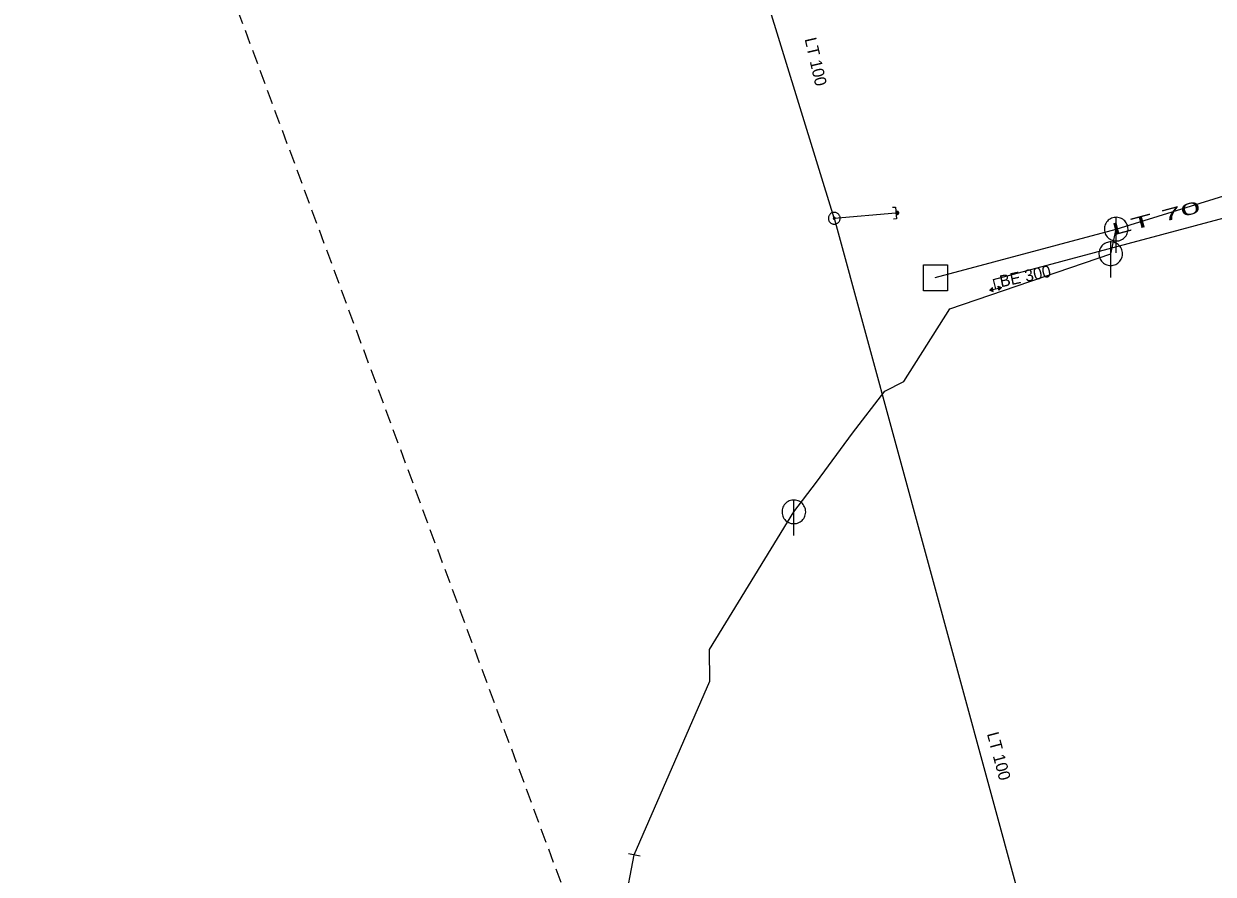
# Model space of a CAD drawing. Extents: x -690254 to -689100, y -975264 to -974703.
# Drawn here: x -689747.9 to -689647.4, y -974992.3 to -974920.4 of the extents above; entities that cross this region are included whole.
import ezdxf

# ---------------------------------------------------------------- set-up
doc = ezdxf.new("R2010")
doc.units = 0
doc.header["$LTSCALE"] = 0.4
doc.linetypes.add('MEDIUM_DASHED', pattern=[4.5, 3, -1.5])
for name, color, linetype, lineweight in [('1', 7, 'Continuous', 13), ('11', 7, 'Continuous', 13), ('14', 7, 'Continuous', 13), ('17', 7, 'Continuous', 25), ('22', 7, 'Continuous', 13), ('28', 7, 'Continuous', 13), ('34', 7, 'Continuous', 13), ('47', 7, 'Continuous', 13), ('63', 7, 'MEDIUM_DASHED', 25), ('9', 7, 'Continuous', 13)]:
    doc.layers.add(name, color=color, linetype=linetype, lineweight=lineweight)

msp = doc.modelspace()

# ---------------------------------------------------------------- linework, layer by layer
at = {"layer": '11'}
msp.add_line((-689656.03, -974939.829), (-689655.57, -974937.75), dxfattribs=at)
for points in [[(-689682.809, -974961.649), (-689680.89, -974959.149), (-689677.85, -974954.989), (-689675.129, -974951.44), (-689673.52, -974950.629), (-689669.64, -974944.5), (-689656.03, -974939.829)], [(-689696.3, -974990.64), (-689689.91, -974975.96), (-689689.94, -974973.28), (-689682.809, -974961.649)], [(-689705.559, -975025.01), (-689705.649, -975017.17), (-689704.62, -975014.579), (-689697.949, -974999.219), (-689696.3, -974990.64)]]:
    msp.add_lwpolyline(points, dxfattribs=at)
at = {"layer": '14'}
msp.add_line((-689674.178, -974936.379), (-689674.067, -974936.377), dxfattribs=at)
at = {"layer": '14', "lineweight": 25}
msp.add_line((-689670.875, -974941.853), (-689655.57, -974937.75), dxfattribs=at)
msp.add_lwpolyline([(-689655.57, -974937.75), (-689631.897, -974930.421), (-689624.679, -974928.186)], dxfattribs=at)
at = {"layer": '17'}
for q in [(-689686.37, -974914.237), (-689674.178, -974936.379), (-689653.94, -975030.302)]:
    msp.add_line((-689679.393, -974936.834), q, dxfattribs=at)
msp.add_lwpolyline([(-689665.933, -974942.022), (-689640.32, -974935.166), (-689625.688, -974930.875), (-689605.756, -974925.377)], dxfattribs=at)
at = {"layer": '22'}
for p, q in [((-689655.57, -974939.75), (-689655.569, -974936.75)), ((-689656.03, -974941.829), (-689656.029, -974938.829)), ((-689682.809, -974963.649), (-689682.808, -974960.649))]:
    msp.add_line(p, q, dxfattribs=at)
for points in [[(-689654.57, -974937.75), (-689654.575, -974937.641), (-689654.593, -974937.533), (-689654.623, -974937.427), (-689654.663, -974937.326), (-689654.715, -974937.229), (-689654.777, -974937.139), (-689654.849, -974937.056), (-689654.929, -974936.982), (-689655.017, -974936.916), (-689655.111, -974936.861), (-689655.211, -974936.816), (-689655.316, -974936.783), (-689655.423, -974936.761), (-689655.532, -974936.751), (-689655.642, -974936.753), (-689655.75, -974936.767), (-689655.857, -974936.792), (-689655.96, -974936.829), (-689656.058, -974936.878), (-689656.15, -974936.936), (-689656.236, -974937.005), (-689656.313, -974937.082), (-689656.382, -974937.168), (-689656.441, -974937.26), (-689656.489, -974937.358), (-689656.526, -974937.461), (-689656.552, -974937.568), (-689656.566, -974937.676), (-689656.569, -974937.786), (-689656.559, -974937.895), (-689656.538, -974938.002), (-689656.504, -974938.106), (-689656.46, -974938.206), (-689656.405, -974938.301), (-689656.339, -974938.389), (-689656.265, -974938.469), (-689656.182, -974938.541), (-689656.092, -974938.603), (-689655.996, -974938.655), (-689655.894, -974938.696), (-689655.789, -974938.726), (-689655.681, -974938.744), (-689655.571, -974938.75), (-689655.462, -974938.744), (-689655.354, -974938.726), (-689655.249, -974938.697), (-689655.147, -974938.656), (-689655.05, -974938.604), (-689654.96, -974938.542), (-689654.877, -974938.471), (-689654.802, -974938.391), (-689654.737, -974938.303), (-689654.681, -974938.209), (-689654.637, -974938.109), (-689654.603, -974938.005), (-689654.581, -974937.897), (-689654.571, -974937.788)], [(-689655.03, -974939.829), (-689655.035, -974939.72), (-689655.053, -974939.612), (-689655.083, -974939.506), (-689655.123, -974939.405), (-689655.175, -974939.308), (-689655.237, -974939.218), (-689655.309, -974939.135), (-689655.389, -974939.061), (-689655.477, -974938.995), (-689655.571, -974938.94), (-689655.671, -974938.895), (-689655.776, -974938.862), (-689655.883, -974938.84), (-689655.992, -974938.83), (-689656.102, -974938.832), (-689656.21, -974938.846), (-689656.317, -974938.871), (-689656.42, -974938.908), (-689656.518, -974938.957), (-689656.61, -974939.015), (-689656.696, -974939.084), (-689656.773, -974939.161), (-689656.842, -974939.247), (-689656.901, -974939.339), (-689656.949, -974939.437), (-689656.986, -974939.54), (-689657.012, -974939.647), (-689657.026, -974939.755), (-689657.029, -974939.865), (-689657.019, -974939.974), (-689656.998, -974940.081), (-689656.964, -974940.185), (-689656.92, -974940.285), (-689656.865, -974940.38), (-689656.799, -974940.468), (-689656.725, -974940.548), (-689656.642, -974940.62), (-689656.552, -974940.682), (-689656.456, -974940.734), (-689656.354, -974940.775), (-689656.249, -974940.805), (-689656.141, -974940.823), (-689656.031, -974940.829), (-689655.922, -974940.823), (-689655.814, -974940.805), (-689655.709, -974940.776), (-689655.607, -974940.735), (-689655.51, -974940.683), (-689655.42, -974940.621), (-689655.337, -974940.55), (-689655.262, -974940.47), (-689655.197, -974940.382), (-689655.141, -974940.288), (-689655.097, -974940.188), (-689655.063, -974940.084), (-689655.041, -974939.976), (-689655.031, -974939.867)], [(-689671.855, -974940.764), (-689669.822, -974940.764), (-689669.822, -974942.957), (-689671.855, -974942.957)], [(-689681.809, -974961.649), (-689681.814, -974961.54), (-689681.832, -974961.432), (-689681.862, -974961.326), (-689681.902, -974961.225), (-689681.954, -974961.128), (-689682.016, -974961.038), (-689682.088, -974960.955), (-689682.168, -974960.881), (-689682.256, -974960.815), (-689682.35, -974960.76), (-689682.45, -974960.715), (-689682.555, -974960.682), (-689682.662, -974960.66), (-689682.771, -974960.65), (-689682.881, -974960.652), (-689682.989, -974960.666), (-689683.096, -974960.691), (-689683.199, -974960.728), (-689683.297, -974960.777), (-689683.389, -974960.835), (-689683.475, -974960.904), (-689683.552, -974960.981), (-689683.621, -974961.067), (-689683.68, -974961.159), (-689683.728, -974961.257), (-689683.765, -974961.36), (-689683.791, -974961.467), (-689683.805, -974961.575), (-689683.808, -974961.685), (-689683.798, -974961.794), (-689683.777, -974961.901), (-689683.743, -974962.005), (-689683.699, -974962.105), (-689683.644, -974962.2), (-689683.578, -974962.288), (-689683.504, -974962.368), (-689683.421, -974962.44), (-689683.331, -974962.502), (-689683.235, -974962.554), (-689683.133, -974962.595), (-689683.028, -974962.625), (-689682.92, -974962.643), (-689682.81, -974962.649), (-689682.701, -974962.643), (-689682.593, -974962.625), (-689682.488, -974962.596), (-689682.386, -974962.555), (-689682.289, -974962.503), (-689682.199, -974962.441), (-689682.116, -974962.37), (-689682.041, -974962.29), (-689681.976, -974962.202), (-689681.92, -974962.108), (-689681.876, -974962.008), (-689681.842, -974961.904), (-689681.82, -974961.796), (-689681.81, -974961.687)]]:
    msp.add_lwpolyline(points, close=True, dxfattribs=at)
at = {"layer": '28'}
msp.add_line((-689696.791, -974990.546), (-689695.809, -974990.734), dxfattribs=at)
at = {"layer": '34'}
for p, q in [((-689666.039, -974942.983), (-689666.093, -974942.762)), ((-689666.011, -974942.997), (-689666.074, -974942.737)), ((-689665.981, -974943.006), (-689666.052, -974942.715)), ((-689665.751, -974942.801), (-689665.932, -974942.022)), ((-689665.546, -974942.581), (-689665.268, -974942.689)), ((-689665.455, -974942.883), (-689665.52, -974942.591)), ((-689665.432, -974942.863), (-689665.49, -974942.601)), ((-689665.413, -974942.838), (-689665.462, -974942.615)), ((-689665.392, -974942.817), (-689665.435, -974942.625)), ((-689665.374, -974942.797), (-689665.409, -974942.635)), ((-689665.35, -974942.776), (-689665.379, -974942.645)), ((-689665.331, -974942.755), (-689665.353, -974942.655)), ((-689665.312, -974942.731), (-689665.325, -974942.669)), ((-689665.287, -974942.71), (-689665.294, -974942.679)), ((-689666.209, -974942.924), (-689666.216, -974942.893)), ((-689666.177, -974942.932), (-689666.192, -974942.871)), ((-689666.149, -974942.945), (-689666.173, -974942.846)), ((-689666.123, -974942.955), (-689666.155, -974942.825)), ((-689666.093, -974942.964), (-689666.132, -974942.802)), ((-689666.067, -974942.974), (-689666.113, -974942.783))]:
    msp.add_line(p, q, dxfattribs=at)
for points in [[(-689666.033, -974942.694), (-689666.235, -974942.913), (-689665.268, -974942.689)], [(-689666.235, -974942.913), (-689665.954, -974943.016), (-689666.033, -974942.694)], [(-689665.268, -974942.689), (-689665.475, -974942.904), (-689665.546, -974942.581)]]:
    msp.add_lwpolyline(points, dxfattribs=at)
at = {"layer": '47'}
for points in [[(-689679.269, -974937.318), (-689679.219, -974937.302), (-689679.171, -974937.281), (-689679.126, -974937.256), (-689679.083, -974937.226), (-689679.043, -974937.191), (-689679.008, -974937.152), (-689678.977, -974937.11), (-689678.95, -974937.065), (-689678.928, -974937.018), (-689678.911, -974936.968), (-689678.899, -974936.917), (-689678.894, -974936.865), (-689678.893, -974936.813), (-689678.898, -974936.761), (-689678.908, -974936.71), (-689678.924, -974936.66), (-689678.945, -974936.612), (-689678.971, -974936.566), (-689679, -974936.524), (-689679.035, -974936.484), (-689679.074, -974936.449), (-689679.116, -974936.417), (-689679.161, -974936.39), (-689679.208, -974936.368), (-689679.258, -974936.352), (-689679.309, -974936.34), (-689679.361, -974936.334), (-689679.413, -974936.334), (-689679.465, -974936.339), (-689679.516, -974936.349), (-689679.566, -974936.365), (-689679.614, -974936.386), (-689679.661, -974936.411), (-689679.702, -974936.441), (-689679.742, -974936.476), (-689679.778, -974936.514), (-689679.809, -974936.556), (-689679.836, -974936.601), (-689679.858, -974936.649), (-689679.874, -974936.699), (-689679.886, -974936.75), (-689679.892, -974936.801), (-689679.892, -974936.854), (-689679.887, -974936.906), (-689679.877, -974936.957), (-689679.861, -974937.007), (-689679.84, -974937.055), (-689679.816, -974937.101), (-689679.785, -974937.143), (-689679.75, -974937.183), (-689679.712, -974937.219), (-689679.67, -974937.249), (-689679.625, -974937.276), (-689679.577, -974937.298), (-689679.527, -974937.315), (-689679.476, -974937.327), (-689679.425, -974937.332), (-689679.372, -974937.333), (-689679.32, -974937.328)], [(-689679.372, -974936.913), (-689679.363, -974936.911), (-689679.356, -974936.907), (-689679.349, -974936.903), (-689679.342, -974936.898), (-689679.335, -974936.892), (-689679.33, -974936.886), (-689679.324, -974936.879), (-689679.32, -974936.872), (-689679.317, -974936.864), (-689679.314, -974936.856), (-689679.312, -974936.847), (-689679.311, -974936.838), (-689679.311, -974936.83), (-689679.311, -974936.822), (-689679.313, -974936.813), (-689679.315, -974936.804), (-689679.319, -974936.797), (-689679.323, -974936.79), (-689679.328, -974936.783), (-689679.334, -974936.776), (-689679.34, -974936.771), (-689679.347, -974936.765), (-689679.354, -974936.761), (-689679.363, -974936.757), (-689679.37, -974936.755), (-689679.379, -974936.753), (-689679.388, -974936.752), (-689679.396, -974936.752), (-689679.404, -974936.752), (-689679.413, -974936.754), (-689679.422, -974936.756), (-689679.429, -974936.76), (-689679.436, -974936.764), (-689679.443, -974936.769), (-689679.45, -974936.775), (-689679.456, -974936.78), (-689679.461, -974936.788), (-689679.465, -974936.795), (-689679.469, -974936.804), (-689679.471, -974936.811), (-689679.473, -974936.82), (-689679.474, -974936.829), (-689679.474, -974936.837), (-689679.474, -974936.845), (-689679.472, -974936.854), (-689679.47, -974936.863), (-689679.466, -974936.87), (-689679.462, -974936.877), (-689679.457, -974936.884), (-689679.451, -974936.891), (-689679.446, -974936.897), (-689679.438, -974936.902), (-689679.431, -974936.906), (-689679.423, -974936.909), (-689679.415, -974936.912), (-689679.406, -974936.914), (-689679.397, -974936.915), (-689679.389, -974936.915), (-689679.381, -974936.915)]]:
    msp.add_lwpolyline(points, close=True, dxfattribs=at)
msp.add_lwpolyline([(-689674.472, -974935.906), (-689674.221, -974935.884), (-689674.134, -974936.873), (-689674.385, -974936.895)], dxfattribs=at)
at = {"layer": '63'}
msp.add_lwpolyline([(-690175.832, -975238.167), (-690201.511, -975156.663), (-690201.511, -975156.663), (-689696.859, -975008.171), (-689696.859, -975008.171), (-689730.354, -974917.735), (-689730.354, -974917.735), (-689127.452, -974763.66), (-689127.452, -974763.66), (-689118.52, -974838.465), (-689118.52, -974838.465), (-689624.288, -974970.21), (-689624.288, -974970.21), (-689593.026, -975070.694), (-689593.026, -975070.694)], close=True, dxfattribs=at)
at = {"layer": '9'}
for points in [[(-689674.193, -974936.377), (-689674.193, -974936.39), (-689674.191, -974936.403), (-689674.188, -974936.416), (-689674.183, -974936.428), (-689674.177, -974936.44), (-689674.17, -974936.451), (-689674.162, -974936.461), (-689674.152, -974936.471), (-689674.142, -974936.479), (-689674.131, -974936.486), (-689674.119, -974936.492), (-689674.107, -974936.497), (-689674.094, -974936.5), (-689674.081, -974936.502), (-689674.068, -974936.504), (-689674.055, -974936.503), (-689674.042, -974936.501), (-689674.029, -974936.498), (-689674.017, -974936.493), (-689674.005, -974936.487), (-689673.994, -974936.48), (-689673.984, -974936.472), (-689673.974, -974936.462), (-689673.966, -974936.452), (-689673.959, -974936.441), (-689673.953, -974936.429), (-689673.948, -974936.417), (-689673.945, -974936.404), (-689673.943, -974936.391), (-689673.941, -974936.378), (-689673.942, -974936.365), (-689673.944, -974936.352), (-689673.947, -974936.339), (-689673.952, -974936.327), (-689673.958, -974936.315), (-689673.965, -974936.304), (-689673.973, -974936.294), (-689673.983, -974936.284), (-689673.993, -974936.276), (-689674.004, -974936.269), (-689674.016, -974936.263), (-689674.028, -974936.258), (-689674.041, -974936.255), (-689674.054, -974936.253), (-689674.067, -974936.252), (-689674.08, -974936.252), (-689674.093, -974936.254), (-689674.106, -974936.257), (-689674.118, -974936.262), (-689674.13, -974936.268), (-689674.141, -974936.275), (-689674.151, -974936.283), (-689674.161, -974936.293), (-689674.169, -974936.303), (-689674.176, -974936.314), (-689674.182, -974936.326), (-689674.187, -974936.338), (-689674.19, -974936.351), (-689674.192, -974936.364)], [(-689674.173, -974936.377), (-689674.174, -974936.388), (-689674.172, -974936.399), (-689674.169, -974936.41), (-689674.165, -974936.42), (-689674.16, -974936.43), (-689674.154, -974936.439), (-689674.147, -974936.448), (-689674.139, -974936.456), (-689674.13, -974936.463), (-689674.121, -974936.469), (-689674.111, -974936.474), (-689674.101, -974936.478), (-689674.09, -974936.481), (-689674.079, -974936.484), (-689674.068, -974936.484), (-689674.057, -974936.484), (-689674.046, -974936.482), (-689674.035, -974936.479), (-689674.025, -974936.475), (-689674.015, -974936.47), (-689674.006, -974936.464), (-689673.997, -974936.457), (-689673.989, -974936.449), (-689673.982, -974936.44), (-689673.976, -974936.431), (-689673.971, -974936.421), (-689673.967, -974936.411), (-689673.964, -974936.4), (-689673.962, -974936.389), (-689673.961, -974936.378), (-689673.961, -974936.367), (-689673.963, -974936.356), (-689673.966, -974936.345), (-689673.97, -974936.335), (-689673.975, -974936.325), (-689673.981, -974936.316), (-689673.988, -974936.307), (-689673.996, -974936.299), (-689674.005, -974936.292), (-689674.014, -974936.286), (-689674.024, -974936.281), (-689674.034, -974936.277), (-689674.045, -974936.274), (-689674.056, -974936.272), (-689674.067, -974936.272), (-689674.078, -974936.271), (-689674.089, -974936.273), (-689674.1, -974936.276), (-689674.11, -974936.28), (-689674.12, -974936.285), (-689674.129, -974936.291), (-689674.138, -974936.298), (-689674.146, -974936.306), (-689674.153, -974936.315), (-689674.159, -974936.324), (-689674.164, -974936.334), (-689674.168, -974936.344), (-689674.171, -974936.355), (-689674.173, -974936.366)], [(-689674.154, -974936.377), (-689674.154, -974936.386), (-689674.153, -974936.395), (-689674.15, -974936.404), (-689674.147, -974936.412), (-689674.143, -974936.42), (-689674.138, -974936.428), (-689674.132, -974936.435), (-689674.126, -974936.441), (-689674.119, -974936.447), (-689674.111, -974936.452), (-689674.103, -974936.456), (-689674.095, -974936.459), (-689674.086, -974936.462), (-689674.077, -974936.463), (-689674.068, -974936.465), (-689674.059, -974936.464), (-689674.05, -974936.463), (-689674.041, -974936.46), (-689674.033, -974936.457), (-689674.025, -974936.453), (-689674.017, -974936.448), (-689674.01, -974936.442), (-689674.004, -974936.436), (-689673.998, -974936.429), (-689673.993, -974936.421), (-689673.989, -974936.413), (-689673.986, -974936.405), (-689673.983, -974936.396), (-689673.982, -974936.387), (-689673.98, -974936.378), (-689673.981, -974936.369), (-689673.982, -974936.36), (-689673.985, -974936.351), (-689673.988, -974936.343), (-689673.992, -974936.335), (-689673.997, -974936.327), (-689674.003, -974936.32), (-689674.009, -974936.314), (-689674.016, -974936.308), (-689674.024, -974936.303), (-689674.032, -974936.299), (-689674.04, -974936.296), (-689674.049, -974936.293), (-689674.058, -974936.292), (-689674.067, -974936.291), (-689674.076, -974936.291), (-689674.085, -974936.292), (-689674.094, -974936.295), (-689674.102, -974936.298), (-689674.11, -974936.302), (-689674.118, -974936.307), (-689674.125, -974936.313), (-689674.131, -974936.319), (-689674.137, -974936.326), (-689674.142, -974936.334), (-689674.146, -974936.342), (-689674.149, -974936.35), (-689674.152, -974936.359), (-689674.153, -974936.368)], [(-689674.134, -974936.377), (-689674.134, -974936.384), (-689674.133, -974936.391), (-689674.132, -974936.398), (-689674.129, -974936.404), (-689674.126, -974936.41), (-689674.122, -974936.416), (-689674.118, -974936.422), (-689674.113, -974936.427), (-689674.107, -974936.431), (-689674.101, -974936.435), (-689674.095, -974936.438), (-689674.089, -974936.441), (-689674.082, -974936.442), (-689674.075, -974936.445), (-689674.068, -974936.445), (-689674.061, -974936.445), (-689674.054, -974936.443), (-689674.047, -974936.442), (-689674.041, -974936.439), (-689674.034, -974936.436), (-689674.029, -974936.432), (-689674.023, -974936.428), (-689674.018, -974936.423), (-689674.014, -974936.417), (-689674.01, -974936.411), (-689674.007, -974936.405), (-689674.004, -974936.399), (-689674.002, -974936.392), (-689674.001, -974936.385), (-689674, -974936.378), (-689674, -974936.371), (-689674.001, -974936.364), (-689674.003, -974936.357), (-689674.006, -974936.351), (-689674.009, -974936.344), (-689674.013, -974936.339), (-689674.017, -974936.333), (-689674.022, -974936.328), (-689674.028, -974936.324), (-689674.033, -974936.32), (-689674.04, -974936.317), (-689674.046, -974936.314), (-689674.053, -974936.312), (-689674.06, -974936.311), (-689674.067, -974936.311), (-689674.074, -974936.311), (-689674.081, -974936.311), (-689674.088, -974936.313), (-689674.094, -974936.316), (-689674.1, -974936.319), (-689674.106, -974936.323), (-689674.112, -974936.327), (-689674.117, -974936.332), (-689674.121, -974936.338), (-689674.125, -974936.343), (-689674.128, -974936.35), (-689674.131, -974936.356), (-689674.132, -974936.363), (-689674.134, -974936.37)], [(-689674.114, -974936.377), (-689674.114, -974936.382), (-689674.114, -974936.387), (-689674.113, -974936.392), (-689674.111, -974936.396), (-689674.109, -974936.401), (-689674.106, -974936.405), (-689674.103, -974936.408), (-689674.099, -974936.412), (-689674.096, -974936.415), (-689674.092, -974936.418), (-689674.087, -974936.42), (-689674.083, -974936.422), (-689674.078, -974936.423), (-689674.073, -974936.425), (-689674.068, -974936.425), (-689674.063, -974936.425), (-689674.058, -974936.424), (-689674.053, -974936.423), (-689674.049, -974936.421), (-689674.044, -974936.419), (-689674.04, -974936.416), (-689674.036, -974936.413), (-689674.033, -974936.409), (-689674.03, -974936.406), (-689674.027, -974936.402), (-689674.025, -974936.397), (-689674.023, -974936.393), (-689674.022, -974936.388), (-689674.021, -974936.383), (-689674.02, -974936.378), (-689674.02, -974936.373), (-689674.021, -974936.368), (-689674.022, -974936.363), (-689674.024, -974936.359), (-689674.026, -974936.354), (-689674.029, -974936.35), (-689674.032, -974936.346), (-689674.035, -974936.343), (-689674.039, -974936.34), (-689674.043, -974936.337), (-689674.048, -974936.335), (-689674.052, -974936.333), (-689674.057, -974936.332), (-689674.062, -974936.331), (-689674.067, -974936.331), (-689674.072, -974936.331), (-689674.077, -974936.332), (-689674.082, -974936.332), (-689674.086, -974936.334), (-689674.091, -974936.336), (-689674.095, -974936.339), (-689674.098, -974936.342), (-689674.102, -974936.345), (-689674.105, -974936.349), (-689674.108, -974936.353), (-689674.11, -974936.358), (-689674.112, -974936.362), (-689674.113, -974936.367), (-689674.114, -974936.372)], [(-689674.094, -974936.377), (-689674.094, -974936.38), (-689674.095, -974936.383), (-689674.094, -974936.385), (-689674.093, -974936.388), (-689674.092, -974936.391), (-689674.09, -974936.393), (-689674.088, -974936.395), (-689674.086, -974936.397), (-689674.084, -974936.399), (-689674.082, -974936.401), (-689674.079, -974936.403), (-689674.076, -974936.404), (-689674.074, -974936.404), (-689674.071, -974936.405), (-689674.068, -974936.405), (-689674.065, -974936.405), (-689674.062, -974936.405), (-689674.059, -974936.404), (-689674.057, -974936.403), (-689674.054, -974936.402), (-689674.052, -974936.4), (-689674.049, -974936.398), (-689674.047, -974936.396), (-689674.046, -974936.394), (-689674.044, -974936.392), (-689674.043, -974936.389), (-689674.041, -974936.386), (-689674.041, -974936.384), (-689674.04, -974936.381), (-689674.039, -974936.378), (-689674.04, -974936.375), (-689674.04, -974936.372), (-689674.041, -974936.369), (-689674.042, -974936.367), (-689674.043, -974936.364), (-689674.045, -974936.362), (-689674.046, -974936.359), (-689674.048, -974936.357), (-689674.051, -974936.356), (-689674.053, -974936.354), (-689674.056, -974936.353), (-689674.058, -974936.352), (-689674.061, -974936.351), (-689674.064, -974936.351), (-689674.067, -974936.35), (-689674.07, -974936.351), (-689674.073, -974936.35), (-689674.075, -974936.352), (-689674.078, -974936.352), (-689674.081, -974936.353), (-689674.083, -974936.355), (-689674.085, -974936.356), (-689674.087, -974936.358), (-689674.089, -974936.361), (-689674.091, -974936.363), (-689674.092, -974936.366), (-689674.093, -974936.368), (-689674.094, -974936.371), (-689674.094, -974936.374)], [(-689674.075, -974936.377), (-689674.075, -974936.379), (-689674.075, -974936.379), (-689674.074, -974936.379), (-689674.074, -974936.381), (-689674.075, -974936.382), (-689674.073, -974936.382), (-689674.073, -974936.382), (-689674.073, -974936.384), (-689674.073, -974936.384), (-689674.072, -974936.385), (-689674.07, -974936.385), (-689674.07, -974936.385), (-689674.07, -974936.386), (-689674.068, -974936.386), (-689674.068, -974936.386), (-689674.067, -974936.386), (-689674.066, -974936.386), (-689674.066, -974936.385), (-689674.065, -974936.385), (-689674.063, -974936.385), (-689674.063, -974936.384), (-689674.063, -974936.384), (-689674.062, -974936.383), (-689674.062, -974936.383), (-689674.06, -974936.382), (-689674.06, -974936.381), (-689674.059, -974936.38), (-689674.059, -974936.38), (-689674.059, -974936.379), (-689674.059, -974936.378), (-689674.059, -974936.377), (-689674.059, -974936.376), (-689674.059, -974936.376), (-689674.06, -974936.375), (-689674.06, -974936.374), (-689674.061, -974936.373), (-689674.061, -974936.373), (-689674.062, -974936.372), (-689674.062, -974936.372), (-689674.063, -974936.371), (-689674.064, -974936.371), (-689674.065, -974936.37), (-689674.065, -974936.37), (-689674.066, -974936.37), (-689674.067, -974936.37), (-689674.068, -974936.37), (-689674.069, -974936.37), (-689674.069, -974936.37), (-689674.07, -974936.371), (-689674.071, -974936.37), (-689674.072, -974936.372), (-689674.072, -974936.372), (-689674.073, -974936.372), (-689674.073, -974936.372), (-689674.074, -974936.374), (-689674.074, -974936.375), (-689674.074, -974936.376), (-689674.075, -974936.376), (-689674.075, -974936.377)]]:
    msp.add_lwpolyline(points, close=True, dxfattribs=at)

# ---------------------------------------------------------------- texts
at = {"layer": '1'}
for s, rotation, p in [('LT 100', 283, (-689681.908, -974921.676)), ('BE 300', 12, (-689665.301, -974942.67)), ('LT 100', 285, (-689666.503, -974980.414))]:
    msp.add_text(s, height=1, rotation=rotation, dxfattribs=at).set_placement(p)
at = {"layer": '1', "width": 2.25}
msp.add_text('LT 70 ', height=1, rotation=15, dxfattribs=at).set_placement((-689655.796, -974938.288))

doc.saveas('drawing.dxf')
